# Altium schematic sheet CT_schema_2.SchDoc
size 276 x 169 mm
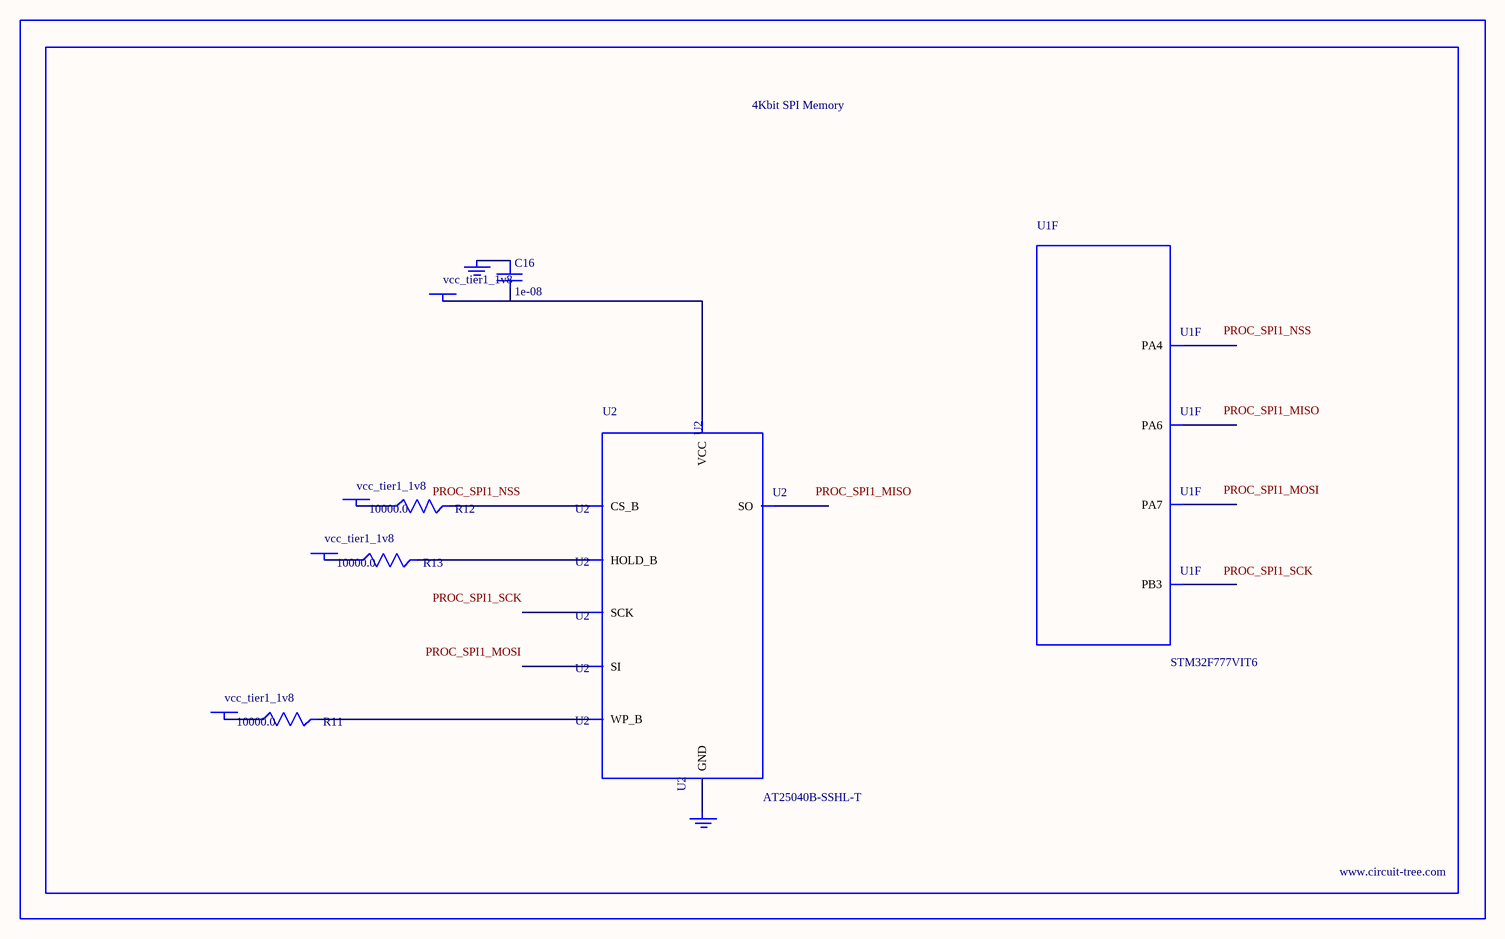
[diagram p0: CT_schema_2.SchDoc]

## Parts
BORDER1  (no value)
C16  1e-08  [C0402]
GND_INSTANCE_1_0  (no value)
GND_INSTANCE_1_1  (no value)
POWER_INSTANCE_1_0  vcc_tier1_1v8
POWER_INSTANCE_1_1  vcc_tier1_1v8
POWER_INSTANCE_1_2  vcc_tier1_1v8
POWER_INSTANCE_1_3  vcc_tier1_1v8
R11  10000.0  [R0603]
R12  10000.0  [R0603]
R13  10000.0  [R0603]
U1  STM32F777VIT6  [LQFP100]  (part F of 11)
U2  AT25040B-SSHL-T  [SOIC-8]

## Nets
NetC16_1: C16.1 GND_INSTANCE_1_0.0(GND)
NetC16_2: C16.2 POWER_INSTANCE_1_3.0(PWR) U2.8(VCC)
NetGND_INSTANCE_1_1_0: GND_INSTANCE_1_1.0(GND) U2.4(GND)
NetPOWER_INSTANCE_1_0_0: POWER_INSTANCE_1_0.0(PWR) R12.1
NetPOWER_INSTANCE_1_1_0: POWER_INSTANCE_1_1.0(PWR) R11.1
NetPOWER_INSTANCE_1_2_0: POWER_INSTANCE_1_2.0(PWR) R13.1
NetR11_2: R11.2 U2.3(WP_B)
NetR12_2: R12.2 U2.1(CS_B)
NetR13_2: R13.2 U2.7(HOLD_B)

Not connected (* = marked no-connect by the designer): U1 28(PA4) 30(PA6) 31(PA7) 89(PB3); U2 2(SO) 5(SI) 6(SCK)

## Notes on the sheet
- Labels drawn without touching a wire or pin: PROC_SPI1_MISO, PROC_SPI1_MOSI, PROC_SPI1_NSS, PROC_SPI1_SCK

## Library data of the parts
BORDER1 = BORDER_PAGE1
C16 = C0402C103K3RAC
GND_INSTANCE_1_0 GND_INSTANCE_1_1 = GND
POWER_INSTANCE_1_0-POWER_INSTANCE_1_3 = PWR
R11-R13 = RC0603JR-0710KL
